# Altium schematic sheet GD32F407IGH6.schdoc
size 127 x 101 mm
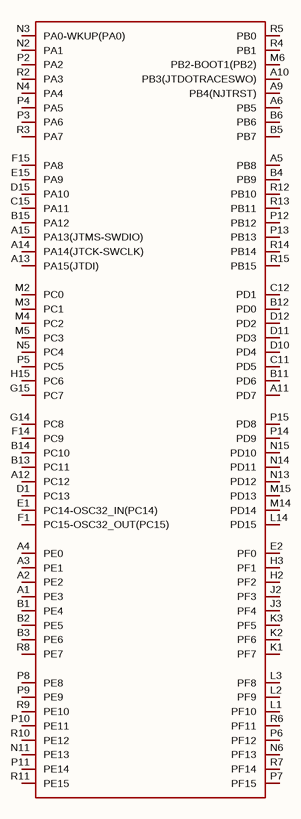
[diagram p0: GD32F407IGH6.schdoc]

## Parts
U?  gd32f407igh6  [BGA-201_L10.0-W10.0-P0.65-TL_GD32F450XXX]  (value not drawn)  (part A of 3)

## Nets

Not connected (* = marked no-connect by the designer): U? A1(PE3) A2(PE2) A3(PE1) A4(PE0) A5(PB8) A6(PB5) A9(PB4(NJTRST)) A10(PB3(JTDOTRACESWO)) A11(PD7) A12(PC12) A13(PA15(JTDI)) A14(PA14(JTCK-SWCLK)) A15(PA13(JTMS-SWDIO)) B1(PE4) B2(PE5) B3(PE6) B4(PB9) B5(PB7) B6(PB6) B11(PD6) B12(PD0) B13(PC11) B14(PC10) B15(PA12) C11(PD5) C12(PD1) C15(PA11) D1(PC13) D10(PD4) D11(PD3) D12(PD2) D15(PA10) E1(PC14-OSC32_IN(PC14)) E2(PF0) E15(PA9) F1(PC15-OSC32_OUT(PC15)) F14(PC9) F15(PA8) G14(PC8) G15(PC7) H2(PF2) H3(PF1) H15(PC6) J2(PF3) J3(PF4) K1(PF7) K2(PF6) K3(PF5) L1(PF10) L2(PF9) L3(PF8) L14(PD15) M2(PC0) M3(PC1) M4(PC2) M5(PC3) M6(PB2-BOOT1(PB2)) M14(PD14) M15(PD13) N2(PA1) N3(PA0-WKUP(PA0)) N4(PA4) N5(PC4) N6(PF13) N11(PE13) N13(PD12) N14(PD11) N15(PD10) P2(PA2) P3(PA6) P4(PA5) P5(PC5) P6(PF12) P7(PF15) P8(PE8) P9(PE9) P10(PE11) P11(PE14) P12(PB12) P13(PB13) P14(PD9) P15(PD8) R2(PA3) R3(PA7) R4(PB1) R5(PB0) R6(PF11) R7(PF14) R8(PE7) R9(PE10) R10(PE12) R11(PE15) R12(PB10) R13(PB11) R14(PB14) R15(PB15)

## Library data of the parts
U? = gd32f407igh6: CPU内核:ARM Cortex-M4;CPU最大主频:168MHz;; Manufacturer: GigaDevice(兆易创新); AddInBom: yes; ModelId: edb09273e1b7436dbcf425ae31c55eab; ModelTransform: 393.7,393.7,0,0,0,0,0,0,0; CPU Maximum Speed: 168MHz; Program Storage Size: 512KB; Program Memory Type: FLASH; Number of I/O: 140; ADC (Bit): 12bit; Voltage - Supply: 2.6V~3.6V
